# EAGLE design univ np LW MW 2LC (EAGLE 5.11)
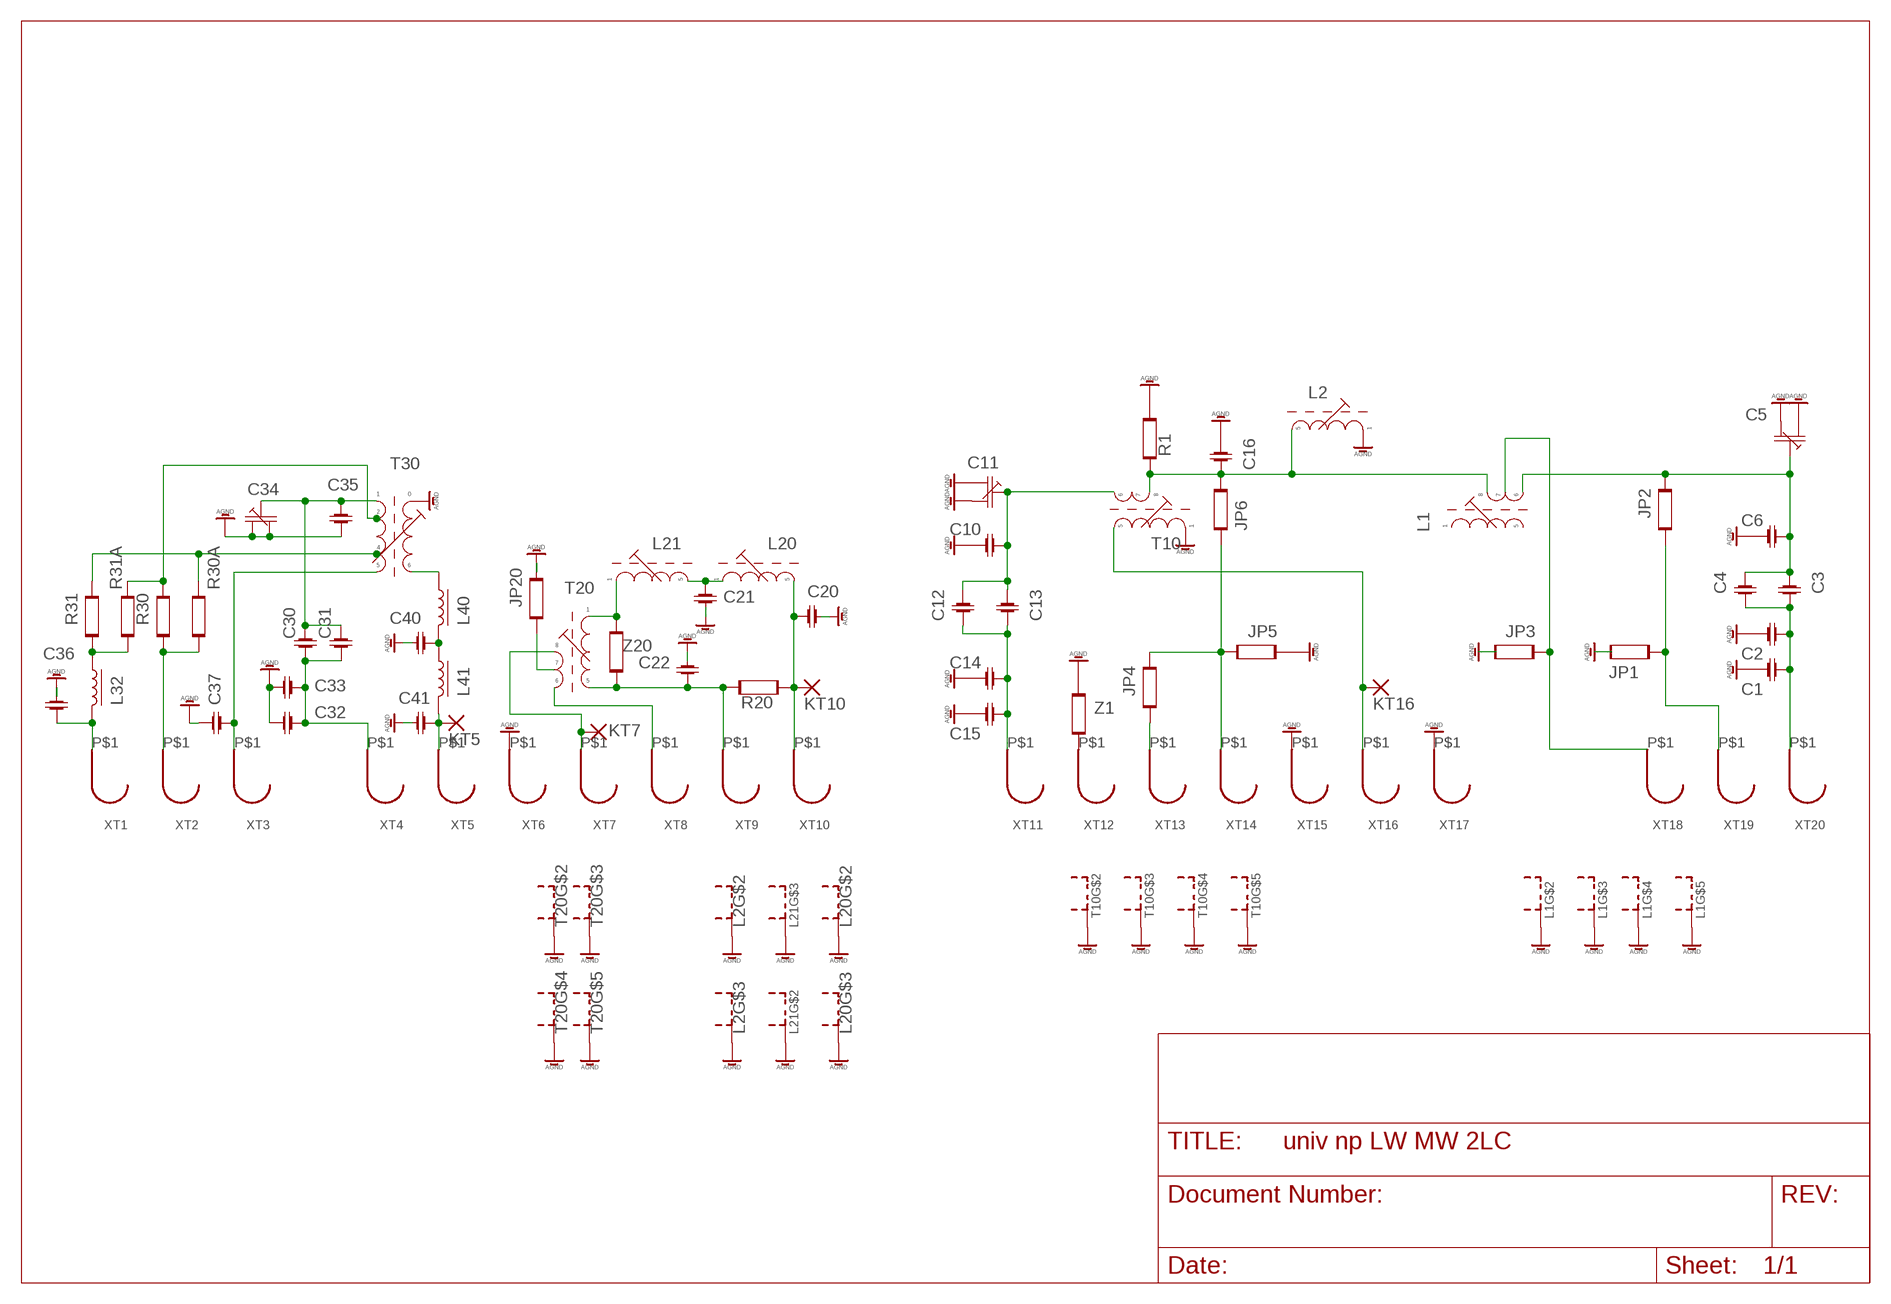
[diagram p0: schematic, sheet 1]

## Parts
C1  C-1206-0805  [RC-SMD-UNIV]
C2  C-1206-0805  [RC-SMD-UNIV]
C3  C-1206-0805  [RC-SMD-UNIV]
C4  C-1206-0805  [RC-SMD-UNIV]
C5  C-TRIM-AM  [C-TRIM-ORIG]
C6  C-1206-0805  [RC-SMD-UNIV]
C10  C-1206-0805  [RC-SMD-UNIV]
C11  C-TRIM-AM  [C-TRIM-ORIG]
C12  C-1206-0805  [RC-SMD-UNIV]
C13  C-1206-0805  [RC-SMD-UNIV]
C14  C-1206-0805  [RC-SMD-UNIV]
C15  C-1206-0805  [RC-SMD-UNIV]
C16  C-1206-0805  [RC-SMD-UNIV]
C20  C-1206-0805  [RC-SMD-UNIV]
C21  C-1206-0805  [RC-SMD-UNIV]
C22  C-1206-0805  [RC-SMD-UNIV]
C30  C-1206-0805  [RC-SMD-UNIV]
C31  C-1206-0805  [RC-SMD-UNIV]
C32  C-1206-0805  [RC-SMD-UNIV]
C33  C-1206-0805  [RC-SMD-UNIV]
C34  C-TRIM-AM  [C-TRIM-ORIG]
C35  C-1206-0805  [RC-SMD-UNIV]
C36  C-1206-0805  [RC-SMD-UNIV]
C37  C-1206-0805  [RC-SMD-UNIV]
C40  C-1206-0805  [RC-SMD-UNIV]
C41  C-1206-0805  [RC-SMD-UNIV]
JP1  R-1206-0805  [RC-SMD-UNIV]
JP2  R-1206-0805  [RC-SMD-UNIV]
JP3  R-1206-0805  [RC-SMD-UNIV]
JP4  R-1206-0805  [RC-SMD-UNIV]
JP5  R-1206-0805  [RC-SMD-UNIV]
JP6  R-1206-0805  [RC-SMD-UNIV]
JP20  R-1206-0805  [RC-SMD-UNIV]
KT5  2,15/1,0  [2,15/1,0]
KT7  2,15/1,0  [2,15/1,0]
KT10  2,15/1,0  [2,15/1,0]
KT16  2,15/1,0  [2,15/1,0]
L1  209-N-T90  [L-10-7-MM]
L2  209-N-L50  [L-7-MM]
L20  209-N-L50  [L-7-MM]
L21  209-N-L50  [L-7-MM]
L32  L-US0207/12  [0207/12]
L40  L-US0207/12  [0207/12]
L41  L-US0207/12  [0207/12]
R1  R-1206-0805  [RC-SMD-UNIV]
R20  R-1206-0805  [RC-SMD-UNIV]
R30  R-1206-0805  [RC-SMD-UNIV]
R30A  R-1206-0805  [RC-SMD-UNIV]
R31  R-1206-0805  [RC-SMD-UNIV]
R31A  R-1206-0805  [RC-SMD-UNIV]
T10  209-N-T90  [L-10-7-MM]
T20  209-N-T90  [L-10-7-MM]
T30  L-MOD-OSC-LWMW  [L-KW-LARGE]
XT1  CONTACT-RF  [CONTACT-RF]
XT2  CONTACT-RF  [CONTACT-RF]
XT3  CONTACT-RF  [CONTACT-RF]
XT4  CONTACT-RF  [CONTACT-RF]
XT5  CONTACT-RF  [CONTACT-RF]
XT6  CONTACT-RF  [CONTACT-RF]
XT7  CONTACT-RF  [CONTACT-RF]
XT8  CONTACT-RF  [CONTACT-RF]
XT9  CONTACT-RF  [CONTACT-RF]
XT10  CONTACT-RF  [CONTACT-RF]
XT11  CONTACT-RF  [CONTACT-RF]
XT12  CONTACT-RF  [CONTACT-RF]
XT13  CONTACT-RF  [CONTACT-RF]
XT14  CONTACT-RF  [CONTACT-RF]
XT15  CONTACT-RF  [CONTACT-RF]
XT16  CONTACT-RF  [CONTACT-RF]
XT17  CONTACT-RF  [CONTACT-RF]
XT18  CONTACT-RF  [CONTACT-RF]
XT19  CONTACT-RF  [CONTACT-RF]
XT20  CONTACT-RF  [CONTACT-RF]
Z1  R-1206-0805  [RC-SMD-UNIV]
Z20  R-1206-0805  [RC-SMD-UNIV]

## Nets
AGND: C1.P$1 C2.P$1 C5.P$6 C5.P$7 C6.P$1 C10.P$1 C11.P$6 C11.P$7 C14.P$1 C15.P$1 C16.P$2 C20.P$2 C21.P$2 C22.P$2 C32.P$2 C33.P$2 C34.P$6 C34.P$7 C35.P$2 C36.P$1 C37.P$2 C40.P$2 C41.P$2 JP1.P$2 JP3.P$1 JP5.P$2 JP20.P$2 L1.11(S) L1.12(S) L1.13(S) L1.14(S) L2.1 L2.P$6(S) L2.P$7(S) L20.P$6(S) L20.P$7(S) L21.P$6(S) L21.P$7(S) R1.P$2 T10.5 T10.11(S) T10.12(S) T10.13(S) T10.14(S) T20.11(S) T20.12(S) T20.13(S) T20.14(S) T30.P$2 XT6.P$1 XT15.P$1 XT17.P$1 Z1.P$2
N$1: C12.P$1 C13.P$1 C14.P$2 C15.P$2 XT11.P$1
N$2: C10.P$2 C11.P$5 C12.P$2 C13.P$2 T10.3
N$3: C3.P$2 C4.P$2 C5.P$5 C6.P$2 JP2.P$2 L1.3
N$4: C1.P$2 C2.P$2 C3.P$1 C4.P$1 XT20.P$1
N$5: XT12.P$1 Z1.P$1
N$6: KT16.1(P) T10.4 XT16.P$1
N$7: C16.P$1 JP6.P$1 L1.1 L2.3 R1.P$1 T10.1
N$9: JP4.P$1 XT13.P$1
N$10: JP3.P$2 L1.2 XT18.P$1
N$11: T20.3 XT8.P$1
N$12: KT7.1(P) T20.1 XT7.P$1
N$13: JP20.P$1 T20.2
N$14: C21.P$1 L20.1 L21.3
N$15: L21.1 T20.5 Z20.P$2
N$16: JP4.P$2 JP5.P$1 JP6.P$2 XT14.P$1
N$17: JP1.P$1 JP2.P$1 XT19.P$1
N$18: C41.P$1 KT5.1(P) L41.2 XT5.P$1
N$19: C30.P$1 C31.P$1 C34.P$5 C35.P$1 T30.P$3
N$20: C22.P$1 R20.P$1 T20.4 XT9.P$1 Z20.P$1
N$21: C30.P$2 C31.P$2 C32.P$1 C33.P$1 XT4.P$1
N$22: R30.P$2 R31A.P$2 T30.P$6
N$23: R30.P$1 R30A.P$1 XT2.P$1
N$24: R30A.P$2 R31.P$2 T30.P$5
N$25: L32.1 R31.P$1 R31A.P$1
N$26: C36.P$2 L32.2 XT1.P$1
N$32: C40.P$1 L40.2 L41.1
N$33: L40.1 T30.P$4
N$34: C37.P$1 T30.P$1 XT3.P$1
N$35: C20.P$1 KT10.1(P) L20.3 R20.P$2 XT10.P$1
Unconnected: L1.4 L1.5 T10.2

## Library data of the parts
C1-C4 C6 C10 C12-C16 C20-C22 C30-C33 C35-C37 C40 C41 = OKEAH:C-1206-0805
C5 C11 C34 = OKEAH:C-TRIM-AM
JP1-JP6 JP20 R1 R20 R30 R30A R31 R31A Z1 Z20 = OKEAH:R-1206-0805
KT5 KT7 KT10 KT16 = single pads:2,15/1,0: THROUGH-HOLE PAD
L1 T10 T20 = OKEAH:209-N-T90
L2 L20 L21 = OKEAH:209-N-L50
L32 L40 L41 = rcl:L-US: INDUCTOR, American symbol
T30 = OKEAH:L-MOD-OSC-LWMW
XT1-XT20 = OKEAH:CONTACT-RF

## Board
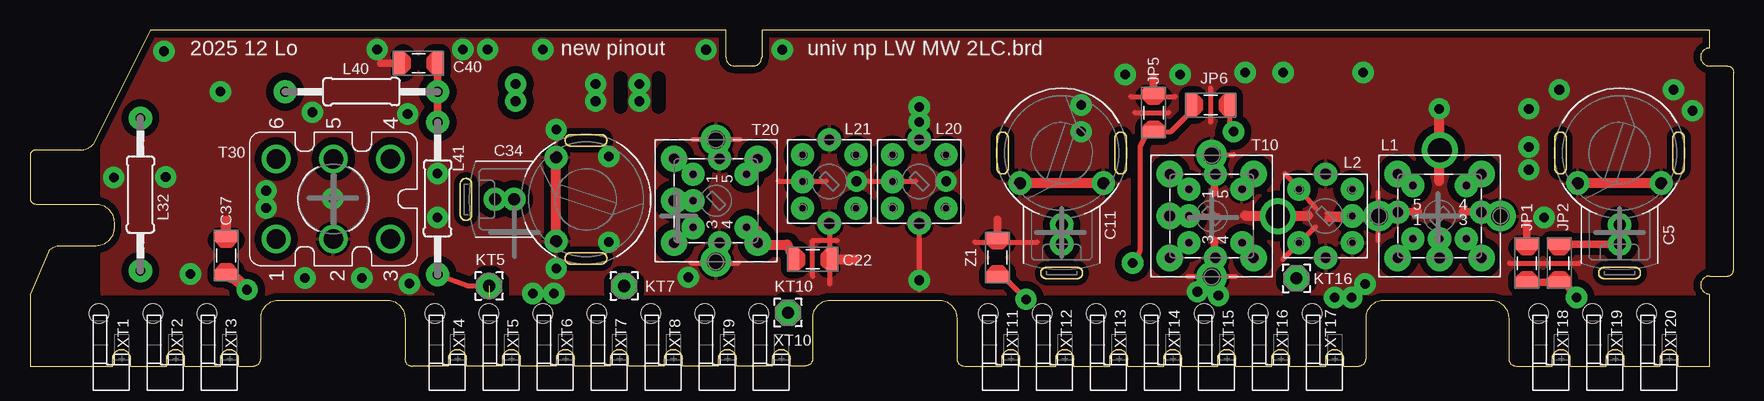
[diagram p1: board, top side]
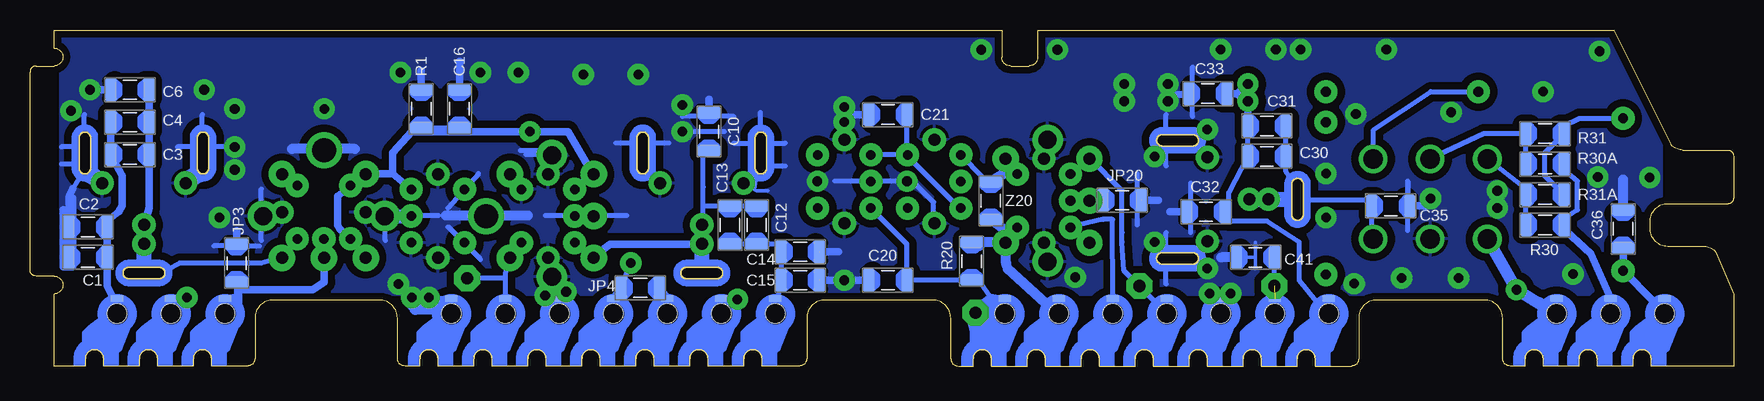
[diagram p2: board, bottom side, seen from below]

Size 142 x 28 mm. Coordinates in mm from the lower left corner, seen from the top.
Outline: 139 segments
Copper layers (1*16): Top 0.035mm / dielectric 1.5mm / Bottom 0.035mm
Design rules "default *": minimum track width 10mil, minimum drill 24mil, track to track 8mil, track to pad 8mil, pad to pad 8mil, via to via 8mil, smd to smd 8mil, copper to edge 8mil, drill to drill 8mil, minimum pad ring 10mil, minimum via ring 8mil, stop-mask expansion 4mil, vias tented up to drill 0mil, thermal gap 10mil
tRestrict: 2 lines
bRestrict: 19 lines

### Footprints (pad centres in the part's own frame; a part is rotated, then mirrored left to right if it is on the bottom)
RC-SMD-UNIV = smd 0.965 x 1.93: P$1 -1.587,0; P$2 1.587,0
C-TRIM-ORIG = drill 1 pad 1.93 round: P$4 7.58,0; P$5 5.992,0; P$6 2.5,3.493; P$7 2.5,-3.493
2,15/1,0 = drill 1.016 pad 2.159 octagon: 1 0,0
L-10-7-MM = drill 0.8 pad 1.93 round: 1 -2.223,-1.905; 2 0,-1.905; 3 2.223,-1.905; 4 2.223,2.54; 5 -2.223,2.54 | drill 1 pad 2.184 round: 6 -3.493,-3.493; 7 0,-3.493; 8 3.493,-3.493; 9 3.493,3.493; 10 -3.493,3.493 | drill 1.5 pad 2.54 round: 11 -5.08,0; 14 5.08,0 | drill 1 pad 1.93 round: 12 -3.493,0.318; 13 3.493,0.318
L-7-MM = drill 0.8 pad 1.93 round: 1 -2.223,-2.223; 2 0,-2.223; 3 2.223,-2.223; 4 2.223,2.223; 5 -2.223,2.223 | drill 1 pad 1.93 round: P$6 3.493,0; P$7 -3.493,0
0207/12 = drill 0.813 pad 1.93 round: 1 -6.35,0; 2 6.35,0
L-KW-LARGE = drill 1.6 round: P$1 0,0; P$2 0,4.763; P$3 0,9.525; P$4 -6.668,9.525; P$5 -6.668,4.763; P$6 -6.668,0
CONTACT-RF = smd 1.016 x 0.508 bottom: P$1 1,-5.625 | hole 1.6: 1,-4.375

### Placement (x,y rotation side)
C1  137.16,9.05 0 bottom
C2  137.16,11.59 0 bottom
C3  133.67,17.62 0 bottom
C4  133.67,20.32 0 bottom
C5  132.5,17.75 270 top
C6  133.67,23.02 0 bottom
C10  85.41,19.53 270 bottom
C11  86,17.75 270 top
C12  81.44,11.75 90 bottom
C13  83.66,11.75 90 bottom
C14  77.79,9.53 180 bottom
C15  77.79,7.15 180 bottom
C16  106.2,21.43 90 bottom
C20  70.48,7.15 180 bottom
C21  70.48,20.96 180 bottom
C22  65.25,8.89 0 top
C30  38.89,17.46 180 bottom
C31  38.89,20 180 bottom
C32  43.97,12.86 180 bottom
C33  43.81,22.7 180 bottom
C34  46.34,13.89 180 top
C35  28.57,13.34 0 bottom
C36  9.21,11.43 270 bottom
C37  16.35,9.21 90 top
C40  32.38,25.24 180 top
C41  39.85,9.05 180 bottom
JP1  124.78,8.57 90 top
JP2  127.48,8.57 90 top
JP3  124.78,8.58 270 bottom
JP4  91.12,6.51 180 bottom
JP5  93.66,21.12 90 top
JP6  98.42,21.75 180 top
JP20  50.96,13.81 0 bottom
KT5  38.26,6.67 0 top
KT7  49.53,6.67 0 top
KT10  63.18,4.45 0 top
KT16  105.57,7.3 0 top
L1  117.5,12.5 0 top
L2  108,12.5 90 top
L20  74.12,15.38 270 top
L21  66.62,15.38 270 top
L32  9.21,14.29 270 top
L40  27.62,22.86 0 top
L41  33.97,13.97 270 top
R1  109.38,21.43 90 bottom
R20  63.5,8.73 270 bottom
R30  15.72,11.75 180 bottom
R30A  15.72,16.83 180 bottom
R31  15.72,19.37 180 bottom
R31A  15.72,14.29 180 bottom
T10  98.5,12.5 270 top
T20  57.17,13.77 270 top
T30  20.52,10.59 270 top
XT1  6.75,0 180 top
XT2  11.25,0 180 top
XT3  15.75,0 180 top
XT4  34.75,0 180 top
XT5  39.25,0 180 top
XT6  43.75,0 180 top
XT7  48.25,0 180 top
XT8  52.75,0 180 top
XT9  57.25,0 180 top
XT10  61.75,0 180 top
XT11  80.88,0 180 top
XT12  85.38,0 180 top
XT13  89.88,0 180 top
XT14  94.38,0 180 top
XT15  98.88,0 180 top
XT16  103.38,0 180 top
XT17  107.88,0 180 top
XT18  126.75,0 180 top
XT19  131.25,0 180 top
XT20  135.75,0 180 top
Z1  80.64,9.05 90 top
Z20  61.91,13.77 90 bottom

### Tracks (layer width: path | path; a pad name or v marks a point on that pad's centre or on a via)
AGND  (via drill 0.8 pad 1.78)  (3 unrouted)
  Top 0.406: 67.31,10.48 65.25,10.48 65.25,7.46 | 66.67,6.83 66.67,12.07 | 74.14,6.35 74.14,11.59 | 78.74,10.32 83.98,10.32 | 92.08,21.12 94.93,21.12 | 98.42,20.32 98.42,23.18 | 98.42,17.62 100.33,17.62 | 96.52,7.46 100.49,7.46 | 108.11,12.7 112.08,12.7 | 108.11,12.39 112.08,12.39 | 108.11,12.23 112.08,12.23 | 112.39,10.48 112.39,14.45 | 55.24,18.89 59.21,18.89 | 55.09,8.58 59.05,8.58 | 62.39,15.4 66.36,15.4 | 69.85,15.4 73.82,15.4 | 123.35,8.57 129.22,8.57 | T10.11 T10.12 | 91.74,22.45 95.48,22.45 | 104.62,16.04 107.16,13.18 | 104.46,8.89 107.16,11.59 | 95.09,12.54 99.06,12.54
  Top 0.61: 29.21,25.24 C40.P$2 | Z1.P$2 80.64,12.23 | JP1.P$2 124.78,11.91 | JP5.P$2 93.66,24.13 | 98.74,14.45 98.74,15.88 | 98.74,9.05 98.74,10.48 | T10.14 T10.13 | L1.11 L1.12 | 115.73,12.86 114.3,12.86 | 120.81,12.86 119.38,12.86
  Top 0.813: C37.P$2 16.35,12.07 | C22.P$2 68.74,8.89 | 101.28,12.54 106.52,12.54 | 117.47,15.4 117.47,20.64
  Bottom 0.305: 39.85,9.05 39.85,8.1 | 39.85,9.05 39.85,10.32 | 39.85,9.05 C41.P$2 | 80.49,14.61 81.44,14.61 82.55,15.24 81.44,15.72 81.6,14.77
  Bottom 0.406: C35.P$2 27.15,13.97 27.15,15.4 27.15,11.27 | XT6.P$1 v41.91,6.03 | 47.31,9.84 47.31,11.12 | 49.69,11.75 49.69,16.04 | 47.31,16.67 47.31,17.94 | 47.31,19.69 47.31,20.96 | 81.92,18.58 81.92,16.19 C11.P$7 | 80.33,16.67 79.06,16.67 | 80.33,18.58 79.06,18.58 | 91.76,18.58 93.19,18.58 | 88.74,18.58 90.01,18.58 | v97.31,6.19 XT15.P$1 v99.06,5.88 | XT17.P$1 v108.74,5.72 v110.17,5.72 | 83.34,18.58 82.07,18.58 | 84.14,19.53 86.68,19.53 | 81.12,19.85 81.12,21.12 | 45.09,20.8 45.09,24.93 | 45.24,11.12 45.24,15.24 | 47.31,6.83 47.31,8.1 | 83.34,20.8 87.63,20.8 | 122.87,10 124.3,10 126.68,10 | 122.71,10.48 122.71,14.77 | 125.57,18.26 126.68,18.26 | 128.59,18.26 129.7,18.26 | 127.64,19.85 127.64,20.96 | 128.43,16.35 129.06,16.04 C5.P$7 128.27,15.24 127.64,15.56 | 138.27,16.83 139.38,16.83 | 138.27,18.26 139.38,18.26 | 137.48,19.85 137.48,20.96 | 138.43,14.77 137.79,15.72 137.64,15.72 136.53,15.08 136.05,15.88 136.53,16.35 | 107.95,12.54 112.24,12.54 | 110.01,12.86 112.24,12.86 L1.11 112.24,12.07 110.01,12.07 | 98.58,17.94 99.69,17.94 | 99.69,17.94 100.01,17.94 | 99.69,17.94 100.01,17.94 | 100.01,17.94 101.12,17.94 | 99.54,17.62 100.65,17.62 | 74.93,15.4 68.42,15.4 66.67,13.65 66.67,11.75 | 112.39,10.48 112.39,12.7 | 104.62,16.04 107.16,13.18 | 104.46,8.89 107.16,11.59 | 92.23,12.54 99.06,12.54
  Bottom 0.61: C35.P$2 25.56,13.34 | C32.P$2 46.99,12.86 | 47.94,13.81 JP20.P$2 | C33.P$2 46.99,22.55 | C21.P$2 73.66,20.96 | 74.61,9.53 C14.P$1 | 75.72,7.15 C15.P$1 v74.14,7.15 C20.P$2 | 85.41,22.23 85.41,20.96 C10.P$1 | JP1.P$2 124.78,11.27 | C1.P$1 C2.P$1 138.75,14.13 | C6.P$1 136.53,23.02 | 136.53,15.08 C5.P$6 | 139.22,13.02 139.22,8.26 138.43,8.26 138.43,13.97 138.75,14.13 | 138.75,14.13 138.43,14.77 | R1.P$2 | R1.P$2 109.38,24.61 | C16.P$2 | C16.P$2 106.2,25.4
  Bottom 0.813: C36.P$1 9.21,15.56 | C41.P$2 42.7,9.05 | 110.17,5.24 v110.17,5.72 | 100.49,12.54 107.31,12.54 | 114.94,18.1 120.17,18.1
  Bottom 1.016: 110.17,5.24 109.86,4.77 108.27,4.77
  other vias: 6.99,15.72 13.38,7.66 11.31,15.75 22.9,7.34 19.68,13.18 19.69,14.61 27.67,7.34 25.24,13.97 31.63,6.86 11.16,26.23 15.88,22.86 23.54,21.15 43.66,6.03 31.48,20.99 43.86,8.13 28.94,26.39 54.88,7.4 48.26,10.32 36.08,26.39 43.86,19.72 48.26,17.46 38.14,26.39 42.75,26.39 76.36,15.4 62.71,26.35 56.36,26.35 50.8,22.07 47.15,22.07 47.15,23.5 50.8,23.5 33.97,16.04 33.97,12.38 95.89,24.29 91.28,24.29 101.28,24.45 87.63,19.53 87.63,21.75 74.14,20.32 117.47,21.43 104.46,24.45 111.12,24.45 124.94,18.26 124.94,16.35 138.59,21.27 137,23.02 127.48,23.02 111.28,6.83 126.21,12.38 124.94,21.43 68.9,15.4 74.14,21.59
  pour Bottom (isolate 0.61): 10,28 139.5,28 139.5,6 6,6 6,20
  pour Top (isolate 0.61): 6,6 6,20 10,28 58,28 58,25 61,25 61,28 139.5,28 139.5,6
N$1
  Bottom 0.406: 79.69,5.72 C15.P$2 C14.P$2 79.85,10.16 C12.P$1 C13.P$1
  Bottom 0.61: 79.69,5.72 XT11.P$1
N$2
  Bottom 0.406: C12.P$2 C13.P$2 85.88,13.34 | C10.P$2 85.88,17.46 85.88,14.92 85.88,13.34 | 85.88,13.34 85.88,12.54 C11.P$5
  Bottom 0.61: T10.3 95.09,9.05 93.66,10.16 86.04,10.16 C11.P$5
N$3
  Top 0.61: JP2.P$2 132.08,10.16 132.4,10.16 C5.P$5
  Bottom 0.406: L1.3 120.97,9.05 122.71,8.57 129.54,8.57 130.49,8.06 130.97,8.51 132.56,8.51 132.56,10 C5.P$5
  Bottom 0.61: C5.P$5 132.08,13.18 C3.P$2 C4.P$2 C6.P$2
N$4
  Bottom 0.61: XT20.P$1 135.1,5.72 135.57,6.67 C1.P$2 C2.P$2 135.41,12.23 134.62,12.86 134.3,13.34 134.3,15.88 C3.P$1 C4.P$1
N$5  (via drill 0.8 pad 1.78)
  Top 0.406: v83.03,5.56 81.28,7.31 Z1.P$1
  Bottom 0.406: XT12.P$1 83.34,5.24 v83.03,5.56
N$6
  Bottom 0.406: XT16.P$1 102.38,7.31 | 102.38,7.31 102.38,7.75 102,9 T10.4 | 102.38,7.31 KT16.1
N$7  (via drill 0.8 pad 1.78)
  Top 0.406: JP6.P$1 100.01,20.16 v100.33,19.53
  Bottom 0.406: v100.33,19.53 101.92,19.53 | R1.P$1 C16.P$1 | R1.P$1 | R1.P$1 110.01,19.85 110.01,19.53
  Bottom 0.61: T10.1 95.09,16.04 97.16,19.53 v100.33,19.53 101.92,19.53 110.01,19.53 110.17,19.53 111.76,17.78 111.76,16.04 | 111.76,16.04 113.98,16.04 | 111.76,16.04 113.98,16.04 | 111.76,16.04 L2.3 | L1.1 116.2,11.43 116.36,11.75 116.36,14.13 113.98,16.04
N$8  (via drill 2 pad 2.54)
  other vias: 117.5,18
N$9
  Bottom 0.61: XT13.P$1 JP4.P$1
N$10
  Bottom 0.406: XT18.P$1 125.73,5.72 124.78,5.88 JP3.P$2
  Bottom 0.61: XT18.P$1 124.94,5.4 124.62,5.24 124.62,6.35 118.43,6.35 117.47,6.99 117.47,8.89 L1.2 117.47,11.27
N$11
  Bottom 0.406: T20.3 53.66,10.16 55.24,11.59 52.55,12.23 51.75,12.23 XT8.P$1
N$12
  Bottom 0.406: T20.1 53.66,17.31 50.96,14.61 50.96,11.11 50.96,10.32 50.8,7.94 48.26,5.4 | 48.26,5.4 48.1,5.24 XT7.P$1 | KT7.1 48.26,5.4
N$13
  Bottom 0.406: JP20.P$1 53.18,13.81 54.61,13.81 T20.2
N$14
  Bottom 0.406: L21.3 64.45,13.08 68.88,17.5 68.88,17.64 | C21.P$1 68.9,18.42 68.88,17.64 | L20.1 69.69,17.62 68.88,17.64
N$15
  Bottom 0.406: L21.1 62.55,15.72 Z20.P$2
  Bottom 0.813: Z20.P$2 60.8,16.04 T20.5
N$16  (via drill 0.8 pad 1.78)
  Top 0.406: v91.92,8.57 92.39,9.21 92.55,9.69 92.55,11.12 92.55,15.24 92.55,18.26 93.03,19.21 JP5.P$1 95.09,19.53 96.68,21.12 JP6.P$2
  Bottom 0.406: JP4.P$2 | JP4.P$2 v91.92,8.57
  Bottom 0.61: XT14.P$1 JP4.P$2
N$17  (via drill 0.8 pad 1.78)
  Top 0.61: JP1.P$1 JP2.P$1 127.95,6.99 v128.91,5.72
  Bottom 0.61: v128.91,5.72 XT19.P$1
N$18  (1 unrouted)
  Top 0.406: KT5.1 36.51,6.67 L41.2
  Bottom 0.406: KT5.1 C41.P$1
N$19
  Bottom 0.406: 37.15,13.81 37.15,12.54 36.99,12.23 36.67,11.91 36.35,11.75 36.04,11.91 35.72,12.07 35.56,12.39 35.56,13.34 35.56,13.81 30.32,13.81 C35.P$1 30.16,10.8 T30.P$3 | 37.15,13.81 C34.P$5 | C31.P$1 C30.P$1 37.31,16.19 36.99,15.72 36.99,15.56 37.15,15.08 37.15,13.81
N$20
  Top 0.813: C22.P$1 63.13,10.13 60.62,10.13 60.64,11.27 60.64,10.32 T20.4
  Bottom 0.406: XT9.P$1 57.31,5.24
  Bottom 0.813: 60.64,11.27 Z20.P$1 | 60.64,11.27 T20.4 | 57.31,5.24 60.48,8.1 60.64,8.57 60.64,10.32 | 60.64,10.32 60.64,11.27 | R20.P$1 62.87,10 62.71,10.32 60.64,10.32
N$21  (via drill 0.8 pad 1.78)
  Bottom 0.406: C31.P$2 C30.P$2 42.07,14.45 42.07,13.81 | 42.07,13.81 42.07,12.07 38.89,12.07 36.2,10.32 36.2,7.15 34.77,5.4 34.61,5.24 XT4.P$1 | 42.07,13.81 C32.P$1
  Bottom 0.61: 41.43,22.7 v40.48,23.5 | 41.43,22.7 C33.P$1 | 41.43,22.7 v40.48,22.07 C31.P$2
N$22
  Bottom 0.406: T30.P$6 17.3,14.77 R31A.P$2 R30.P$2
N$23
  Bottom 0.406: R30A.P$1 13.97,16.19 13.02,15.4 13.02,13.02 13.97,12.39 R30.P$1
  Bottom 0.61: XT2.P$1 11.91,9.37 13.97,11.27 R30.P$1
N$24
  Bottom 0.406: T30.P$5 20.8,19.37 R31.P$2 R30A.P$2
N$25
  Bottom 0.406: R31A.P$1 15.72,15.88 15.72,17.78 R31.P$1 14.13,20.01 12.86,20.64 L32.1
N$26
  Bottom 0.406: XT1.P$1 6.67,5.4
  Bottom 0.61: C36.P$2 L32.2 6.67,5.4
N$27  (via drill 2 pad 2.54)
  other vias: 104,12.5
N$32
  Top 0.61: C40.P$1 L40.2 L41.1
N$33
  Bottom 0.406: T30.P$4 30,17.26 30,19.69 25.24,22.86 L40.1
N$34  (via drill 0.8 pad 1.78)
  Top 1.016: v18.1,6.35 17.3,7.15 C37.P$1
  Bottom 0.61: 16.19,5.24 15.72,5.24 15.24,5.56 XT3.P$1
  Bottom 1.016: 16.19,5.24 16.03,5.08 v18.1,6.35 T30.P$1
N$35
  Bottom 0.406: XT10.P$1 61.98,5.83 | 61.98,5.83 63.18,4.92 KT10.1 | 61.98,5.83 62.71,6.83 R20.P$2 C20.P$1 68.9,10.16 L20.3
  Bottom 0.813: KT10.1 63.5,3.81 63.18,2.7 62.71,4.92 61.75,5.4

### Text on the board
tPlace: 2025 12 Lo | new pinout | univ np LW MW 2LC.brd
tDocu: ANT Modul | grid placement = 0.125mm | grid SMD = 0.3175mm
